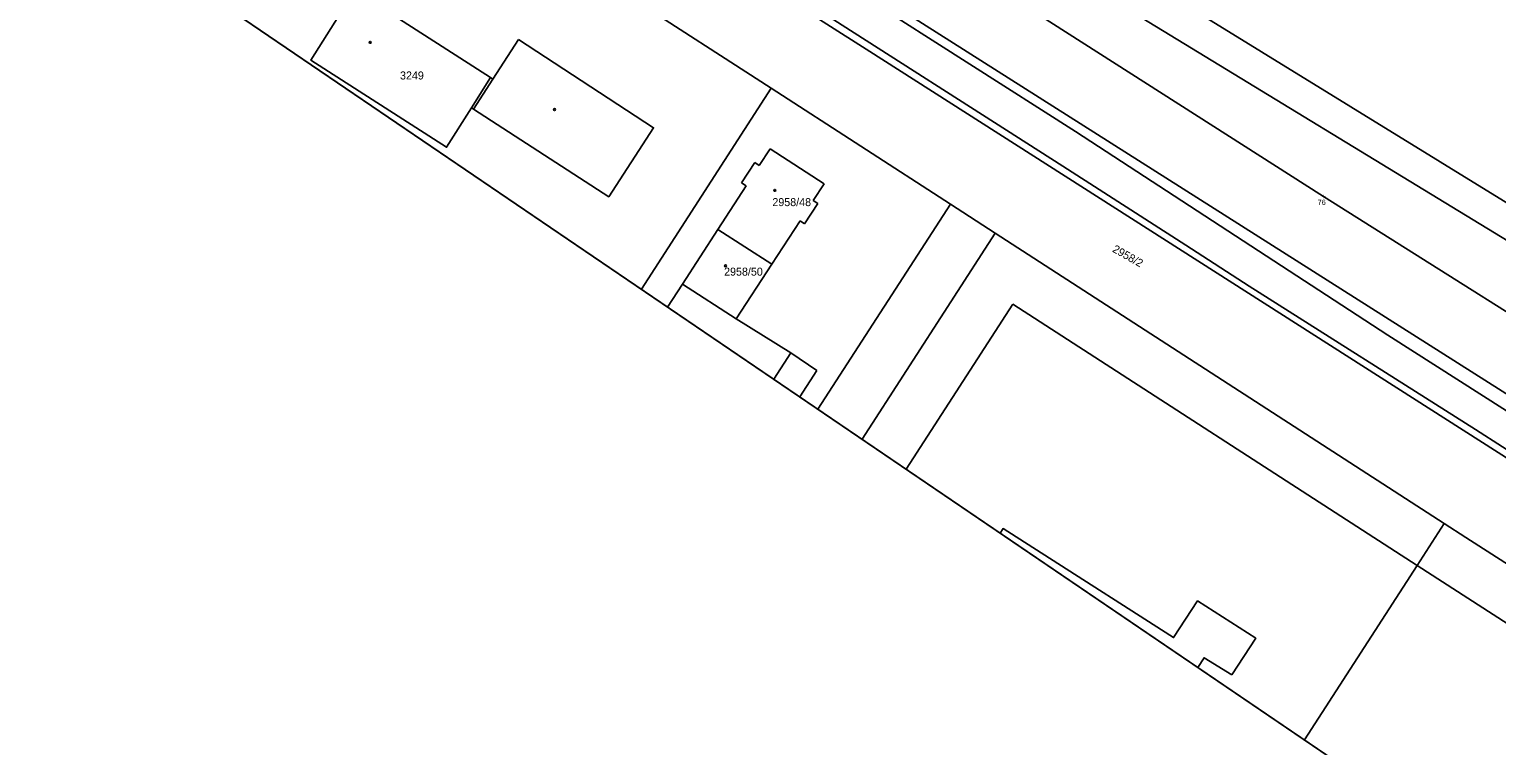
# Model space of a CAD drawing. Extents: x -621058 to -620023, y -1122866 to -1122030.
# Drawn here: x -620841.8 to -620566.7, y -1122586.1 to -1122451.9 of the extents above; entities that cross this region are included whole.
import ezdxf

# ---------------------------------------------------------------- set-up
doc = ezdxf.new("R2010")
doc.units = 0
for name, color, linetype in [('060604_ROZVODY_SEE', 7, 'Continuous'), ('BODY', 7, 'Continuous'), ('BODY POPIS', 7, 'Continuous'), ('RÁMY', 7, 'Continuous'), ('Vrstva 53', 7, 'Continuous'), ('Vrstva 55', 7, 'Continuous'), ('Vrstva 56', 7, 'Continuous'), ('Vrstva 57', 7, 'Continuous')]:
    doc.layers.add(name, color=color, linetype=linetype)

msp = doc.modelspace()

# ---------------------------------------------------------------- linework, layer by layer
at = {"layer": '060604_ROZVODY_SEE'}
msp.add_lwpolyline([(-620443.53, -1122595), (-620456.11, -1122587.12), (-620447.82, -1122572.96), (-620450.95, -1122571.45), (-620470.59, -1122561.48), (-620499.61, -1122545.57), (-620522.04, -1122531.47), (-620538.89, -1122521.21), (-620599.21, -1122483.22), (-620683.52, -1122429.44), (-620756.33, -1122383.52), (-620765.8, -1122398.39)], dxfattribs=at)
at = {"layer": 'RÁMY'}
for points in [[(-620974.7, -1122152.91), (-620106.07, -1122742.82), (-620189.51, -1122865.67), (-621058.13, -1122275.76)], [(-620887.83, -1122211.9), (-620106.07, -1122742.82), (-620189.51, -1122865.67), (-620971.26, -1122334.75)]]:
    msp.add_lwpolyline(points, close=True, dxfattribs=at)
at = {"layer": 'Vrstva 53'}
for p, q in [((-620638.48, -1122446.57), (-620552.09, -1122499.2)), ((-620545.92, -1122532.26), (-620679.51, -1122447.56))]:
    msp.add_line(p, q, dxfattribs=at)
at = {"layer": 'Vrstva 55'}
for p, q in [((-620684.91, -1122455.63), (-620825.92, -1122365.89)), ((-620645.72, -1122471.03), (-620807.67, -1122367.84)), ((-620688.16, -1122408.5), (-620548.9, -1122494.24)), ((-620702.74, -1122462.95), (-620757.34, -1122427.68)), ((-620638.48, -1122446.57), (-620552.09, -1122499.2)), ((-620545.92, -1122532.26), (-620679.51, -1122447.56)), ((-620754.9, -1122461.23), (-620750.13, -1122453.84)), ((-620557.45, -1122536.96), (-620684.91, -1122455.63)), ((-620755.36, -1122460.94), (-620754.9, -1122461.23)), ((-620727.06, -1122500.6), (-620702.74, -1122462.95)), ((-620669.14, -1122484.66), (-620702.74, -1122462.95)), ((-620758.55, -1122466.88), (-620758.93, -1122466.63)), ((-620587.17, -1122509.18), (-620645.72, -1122471.03)), ((-620702.93, -1122474.27), (-620704.97, -1122477.41)), ((-620702.93, -1122474.27), (-620692.81, -1122480.83)), ((-620705.81, -1122476.87), (-620708.28, -1122480.69)), ((-620704.97, -1122477.41), (-620705.81, -1122476.87)), ((-620712.73, -1122489.39), (-620707.44, -1122481.23)), ((-620708.28, -1122480.69), (-620707.44, -1122481.23)), ((-620692.81, -1122480.83), (-620694.86, -1122483.99)), ((-620694.01, -1122484.54), (-620696.48, -1122488.34)), ((-620694.86, -1122483.99), (-620694.01, -1122484.54)), ((-620693.96, -1122523.08), (-620669.14, -1122484.66)), ((-620660.74, -1122490.09), (-620669.14, -1122484.66)), ((-620697.33, -1122487.79), (-620702.63, -1122495.93)), ((-620696.48, -1122488.34), (-620697.33, -1122487.79)), ((-620719.36, -1122499.62), (-620712.73, -1122489.39)), ((-620712.73, -1122489.39), (-620702.63, -1122495.93)), ((-620660.74, -1122490.09), (-620685.68, -1122528.7)), ((-620576.58, -1122544.45), (-620660.74, -1122490.09)), ((-620702.63, -1122495.93), (-620709.28, -1122506.15)), ((-620719.36, -1122499.62), (-620722.14, -1122503.94)), ((-620677.41, -1122534.31), (-620657.43, -1122503.38)), ((-620657.43, -1122503.38), (-620581.67, -1122552.32)), ((-620699.07, -1122512.52), (-620709.28, -1122506.15)), ((-620511.29, -1122557.64), (-620587.17, -1122509.18)), ((-620694.2, -1122515.81), (-620699.07, -1122512.52)), ((-620697.39, -1122520.75), (-620694.2, -1122515.81)), ((-620581.67, -1122552.32), (-620576.58, -1122544.45)), ((-620581.67, -1122552.32), (-620602.78, -1122585))]:
    msp.add_line(p, q, dxfattribs=at)
for points in [[(-620758.93, -1122466.63), (-620763.57, -1122474.01), (-620789, -1122457.71), (-620780.78, -1122444.6), (-620755.36, -1122460.94)], [(-620750.13, -1122453.84), (-620724.79, -1122470.34), (-620733.19, -1122483.27), (-620758.55, -1122466.88)], [(-620659.82, -1122546.26), (-620659.27, -1122545.41), (-620652.1, -1122549.99), (-620627.31, -1122565.82), (-620622.82, -1122558.97), (-620611.91, -1122565.95), (-620616.39, -1122572.84)], [(-620562.8, -1122553.35), (-620572.54, -1122547.06), (-620576.58, -1122544.45)], [(-620581.67, -1122552.32), (-620562.67, -1122564.59), (-620546.5, -1122612), (-620546.78, -1122623.03)], [(-620616.39, -1122572.84), (-620621.58, -1122569.6), (-620622.76, -1122571.43)]]:
    msp.add_lwpolyline(points, dxfattribs=at)
at = {"layer": 'Vrstva 56'}
for p, q in [((-620810.36, -1122373.73), (-620648.08, -1122477.56)), ((-620758.93, -1122466.63), (-620755.36, -1122460.94)), ((-620758.55, -1122466.88), (-620754.9, -1122461.23)), ((-620648.08, -1122477.56), (-620625, -1122492.37)), ((-620625, -1122492.37), (-620613.12, -1122500)), ((-620709.28, -1122506.15), (-620719.36, -1122499.62)), ((-620570.69, -1122526.84), (-620613.12, -1122500)), ((-620699.07, -1122512.52), (-620702.26, -1122517.44)), ((-620504.94, -1122569.2), (-620570.69, -1122526.84))]:
    msp.add_line(p, q, dxfattribs=at)
at = {"layer": 'Vrstva 57'}
for centre in [(-620777.9, -1122454.36), (-620743.34, -1122466.95), (-620702.05, -1122482.08), (-620711.29, -1122496.23)]:
    msp.add_circle(centre, 0.175, dxfattribs=at)

# ---------------------------------------------------------------- texts
at = {"layer": 'BODY'}
msp.add_text('+', height=1, dxfattribs=at).set_placement((-620599.55, -1122483.72))
at = {"layer": 'BODY POPIS'}
msp.add_text('76', height=1, dxfattribs=at).set_placement((-620600.31, -1122484.81))
at = {"layer": 'Vrstva 57'}
for s, p in [('3249', (-620772.31, -1122461.31)), ('2958/48', (-620702.51, -1122485.03)), ('2958/50', (-620711.56, -1122498.05))]:
    msp.add_text(s, height=1.5, dxfattribs=at).set_placement(p)
msp.add_text('2958/2', height=1.5, rotation=330.3, dxfattribs=at).set_placement((-620638.9, -1122493.5))

doc.saveas('drawing.dxf')
